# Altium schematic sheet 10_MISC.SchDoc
size A2; ApprovedBy: DNP; CheckedBy: DNP; Author: DNP; CompanyName: Google LLC; DrawnBy: DNP; Engineer: Bangfei/Michael/Leo; Organization: Google LLC; Address1: 1600 Amphitheatre Parkway; Address2: Mountain View, CA 94043; Address3: DNP; Address4: DNP; DocumentNumber: DNP; Revision: PVT; SheetNumber: 10; SheetTotal: 11; VersionControl_RevNumber: DNP; IsUserConfigurable: DNP
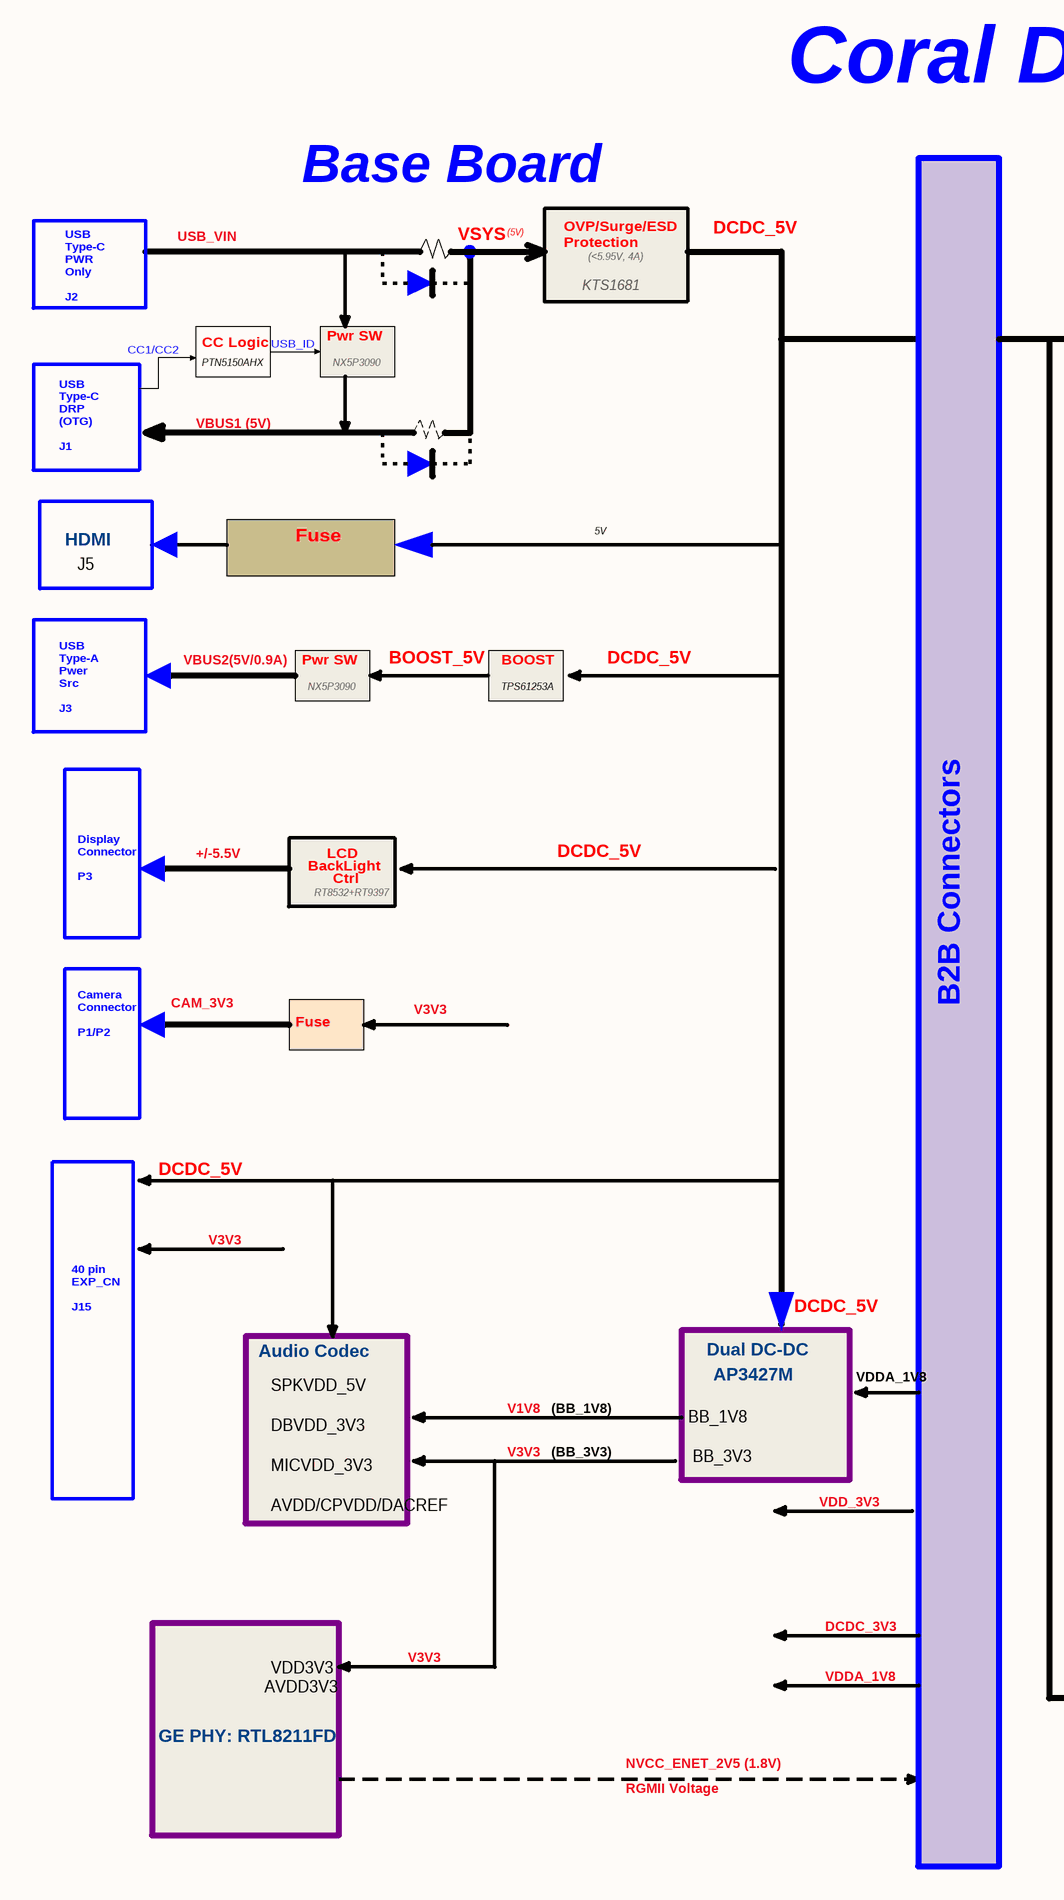
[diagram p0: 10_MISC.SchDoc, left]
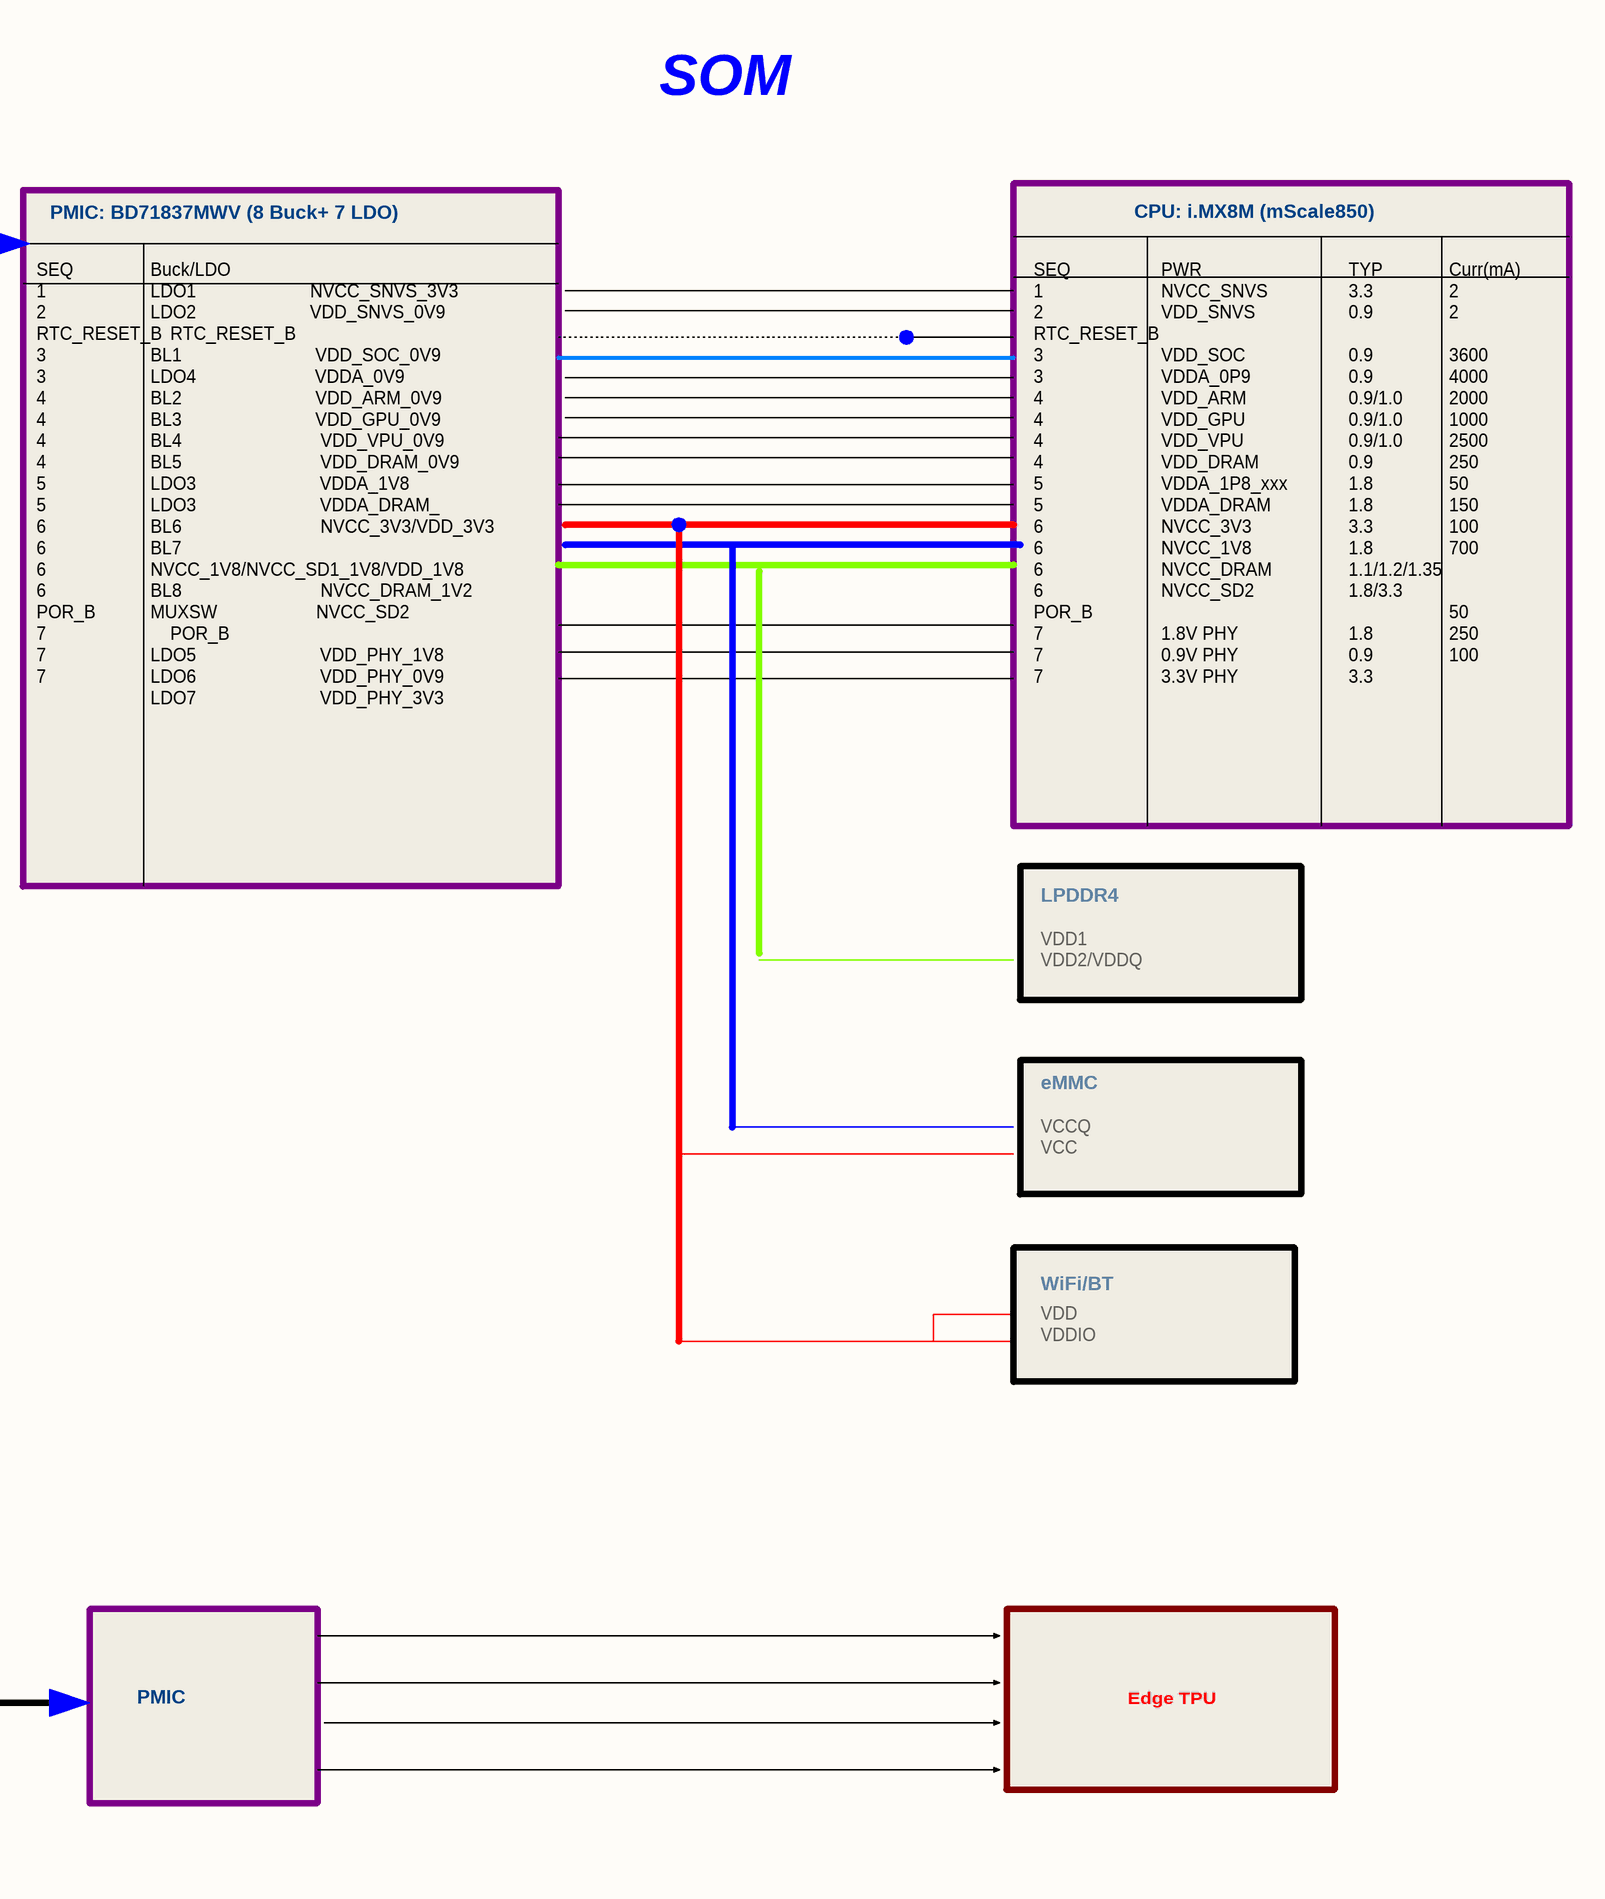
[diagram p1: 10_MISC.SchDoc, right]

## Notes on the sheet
- Coral Dev Board  Power Diagram
- Base Board
- SOM
- USB_VIN
- VSYS
- (5V)
- OVP/Surge/ESD
- Protection
- (<5.95V, 4A)
- DCDC_5V
- USB Type-C
  PWR Only
  J2
- CC1/CC2
- CC Logic
- USB_ID
- Pwr SW
- KTS1681
- PMIC: BD71837MWV (8 Buck+ 7 LDO)
- CPU: i.MX8M (mScale850)
- PTN5150AHX
- NX5P3090
- USB Type-C
  DRP (OTG)
  J1
- VBUS1 (5V)
- 5V
- HDMI
- J5
- Fuse
- USB Type-A
  Pwer Src
  J3
- VBUS2(5V/0.9A)
- BOOST_5V
- BOOST
- TPS61253A
- Display
  Connector
  P3
- +/-5.5V
- BackLight
- RT8532+RT9397
- LCD
- Ctrl
- SEQ
  1
  2
  RTC_RESET_B
  3
  3
  4
  4
  4
  4
  5
  5
  6
  6
  6
  6
  POR_B
  7
  7
  7
- Buck/LDO
  LDO1                       NVCC_SNVS_3V3
  LDO2                       VDD_SNVS_0V9
  RTC_RESET_B
  BL1                           VDD_SOC_0V9
  LDO4                        VDDA_0V9
  BL2                           VDD_ARM_0V9
  BL3                           VDD_GPU_0V9
  BL4                            VDD_VPU_0V9
  BL5                            VDD_DRAM_0V9
  LDO3                         VDDA_1V8
  LDO3                         VDDA_DRAM_
  BL6                            NVCC_3V3/VDD_3V3
  BL7                            NVCC_1V8/NVCC_SD1_1V8/VDD_1V8
  BL8                            NVCC_DRAM_1V2
  MUXSW                    NVCC_SD2
  POR_B
  LDO5                         VDD_PHY_1V8
  LDO6                         VDD_PHY_0V9
  LDO7                         VDD_PHY_3V3
- PWR
  NVCC_SNVS
  VDD_SNVS
  VDD_SOC
  VDDA_0P9
  VDD_ARM
  VDD_GPU
  VDD_VPU
  VDD_DRAM
  VDDA_1P8_xxx
  VDDA_DRAM
  NVCC_3V3
  NVCC_1V8
  NVCC_DRAM
  NVCC_SD2
  1.8V PHY
  0.9V PHY
  3.3V PHY
- TYP
  3.3
  0.9
  0.9
  0.9
  0.9/1.0
  0.9/1.0
  0.9/1.0
  0.9
  1.8
  1.8
  3.3
  1.8
  1.1/1.2/1.35
  1.8/3.3
  1.8
  0.9
  3.3
- Curr(mA)
  2
  2
  3600
  4000
  2000
  1000
  2500
  250
  50
  150
  100
  700
  50
  250
  100
- LPDDR4
- CAM_3V3
- V3V3
- B2B Connectors
- VDD1
  VDD2/VDDQ
- Camera
  Connector
  P1/P2
- eMMC
- VCCQ
  VCC
- 40 pin
  EXP_CN
  J15
- WiFi/BT
- Audio Codec
- Dual DC-DC
- AP3427M
- VDDA_1V8
- VDD
  VDDIO
- V1V8
- (BB_3V3)
- (BB_1V8)
- BB_1V8
  BB_3V3
- SPKVDD_5V
  DBVDD_3V3
  MICVDD_3V3
  AVDD/CPVDD/DACREF
- VDD_3V3
- DCDC_3V3
- AVDD3V3
- VDD3V3
- PMIC
- Edge TPU
- GE PHY: RTL8211FD
- NVCC_ENET_2V5 (1.8V)
- RGMII Voltage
